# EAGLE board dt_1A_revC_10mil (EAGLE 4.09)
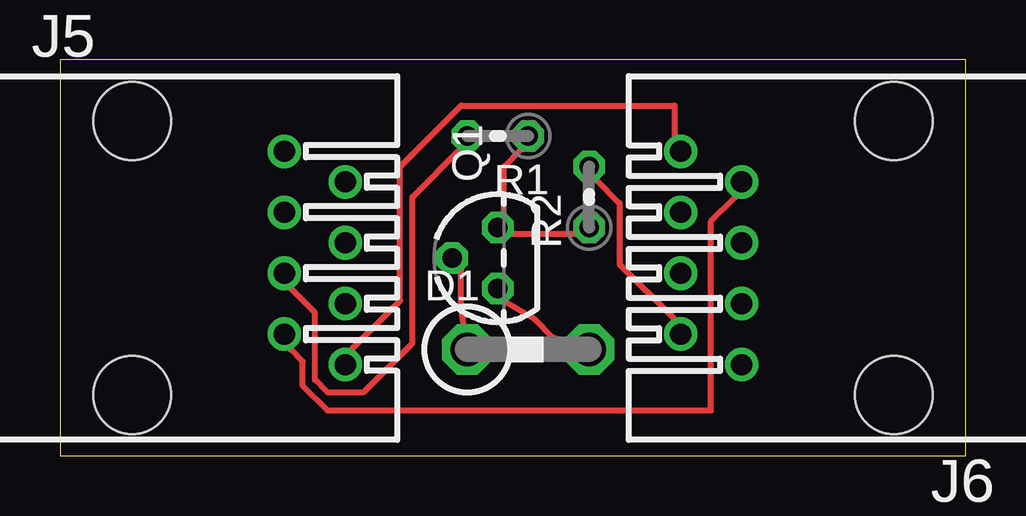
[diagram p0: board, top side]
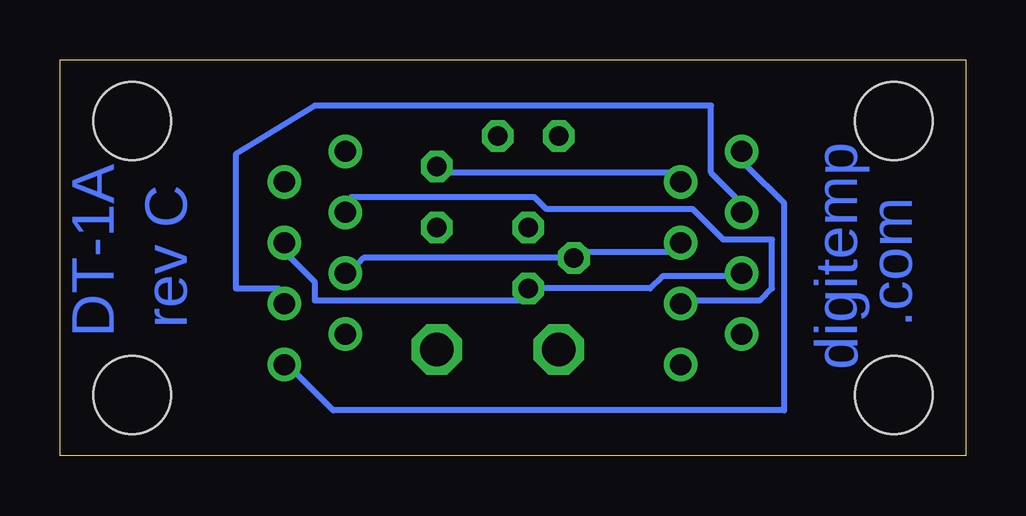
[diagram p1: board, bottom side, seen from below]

Size 37.77 x 16.5 mm. Coordinates in mm from the lower left corner, seen from the top.
Outline: 0,0 37.77,0 37.77,16.5 0,16.5 0,0
Copper layers used: Top, Bottom

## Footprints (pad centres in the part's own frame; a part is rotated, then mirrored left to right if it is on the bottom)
C1702-05 = drill 1.397 octagon: A 2.54,0; C -2.54,0
520251-4 = drill 0.889 round: 1 -4.445,6.35; 2 -3.175,8.89; 3 -1.905,6.35; 4 -0.635,8.89; 5 0.635,6.35; 6 1.905,8.89; 7 3.175,6.35; 8 4.445,8.89 | hole 3.251: -5.715,0; 5.715,0
TO92 = drill 0.813 octagon: 1 1.27,0; 2 0,1.905; 3 -1.27,0
0204V = drill 0.813 octagon: 1 -1.27,0; 2 1.27,0

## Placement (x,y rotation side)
D1  [C1702-05]  19.52,4.44 0 top
J5  [520251-4]  3.01,8.25 270 top
J6  [520251-4]  34.76,8.25 90 top
Q1  DS18S20  [TO92]  18.25,8.25 90 top
R1  [0204V]  18.25,13.33 180 top
R2  [0204V]  22.06,10.79 90 top

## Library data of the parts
D1 = diode
J5 J6 = con-amp
Q1 = transistor-npn
R1 R2 = rcl

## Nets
N$3: J5.1 J6.1
N$4: Q1.1 R1.1 R2.1
N$6: J5.2 J6.2 R2.2
N$7: J5.3 J6.3
N$8: D1.C J5.4 J6.4 Q1.2
N$9: D1.A J5.5 J6.5 Q1.3 R1.2
N$10: J5.6 J6.6
N$11: J5.7 J6.7
N$12: J5.8 J6.8

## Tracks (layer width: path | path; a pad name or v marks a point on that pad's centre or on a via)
N$3
  Bottom 0.254: J5.1 9.11,12.06 7.58,10.54 7.58,1.9 26.38,1.9 27.9,3.42 J6.1
N$4
  Top 0.254: R2.1 21.55,9.27 18.76,9.27 Q1.1 18.5,10.03 18.5,12.06 19.27,12.82 R1.1
N$6
  Top 0.254: J6.2 25.62,5.71 23.33,8 23.33,10.54 22.31,11.55 R2.2
  Bottom 0.254: R2.2 21.55,11.81 12.41,11.81 J5.2
N$7
  Bottom 0.254: J5.3 9.61,10.79 10.63,11.81 10.63,14.6 27.14,14.6 30.44,12.57 30.44,6.98 28.66,6.98 J6.3
N$8
  Top 0.254: D1.C 16.73,6.22 16.73,7.74 Q1.2
  Bottom 0.254: J5.4 12.41,8.5 15.71,8.5 Q1.2 25.11,8.25 25.36,8 J6.4
N$9
  Top 0.254: D1.A 20.54,4.95 19.77,5.71 18.5,6.47 Q1.3 | R1.2 16.73,12.82 14.69,10.79 14.69,4.69 12.66,2.66 11.14,2.66 10.63,3.17 10.63,5.96 9.61,6.98 J5.5
  Bottom 0.254: J6.5 28.16,8.25 27.14,7.23 27.14,6.47 18.5,6.47 Q1.3 13.17,6.98 12.66,7.49 9.87,7.49 J5.5
N$10
  Bottom 0.254: J5.6 11.39,6.47 8.6,6.47 8.09,6.98 8.09,9.01 10.12,9.01 11.39,10.28 17.49,10.28 18,10.79 25.62,10.79 J6.6
N$11
  Top 0.254: J5.7 9.61,4.44 10.12,3.93 10.12,2.92 11.14,1.9 27.14,1.9 27.14,9.77 28.16,10.79 J6.7
N$12
  Top 0.254: J5.8 12.15,4.44 14.19,6.47 14.19,12.06 16.73,14.6 25.62,14.6 25.62,13.33 J6.8

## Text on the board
Bottom: digitemp | rev C | .com | DT-1A
tNames: J5 | R1 | Q1 | R2 | D1 | J6
tValues: DS18S20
